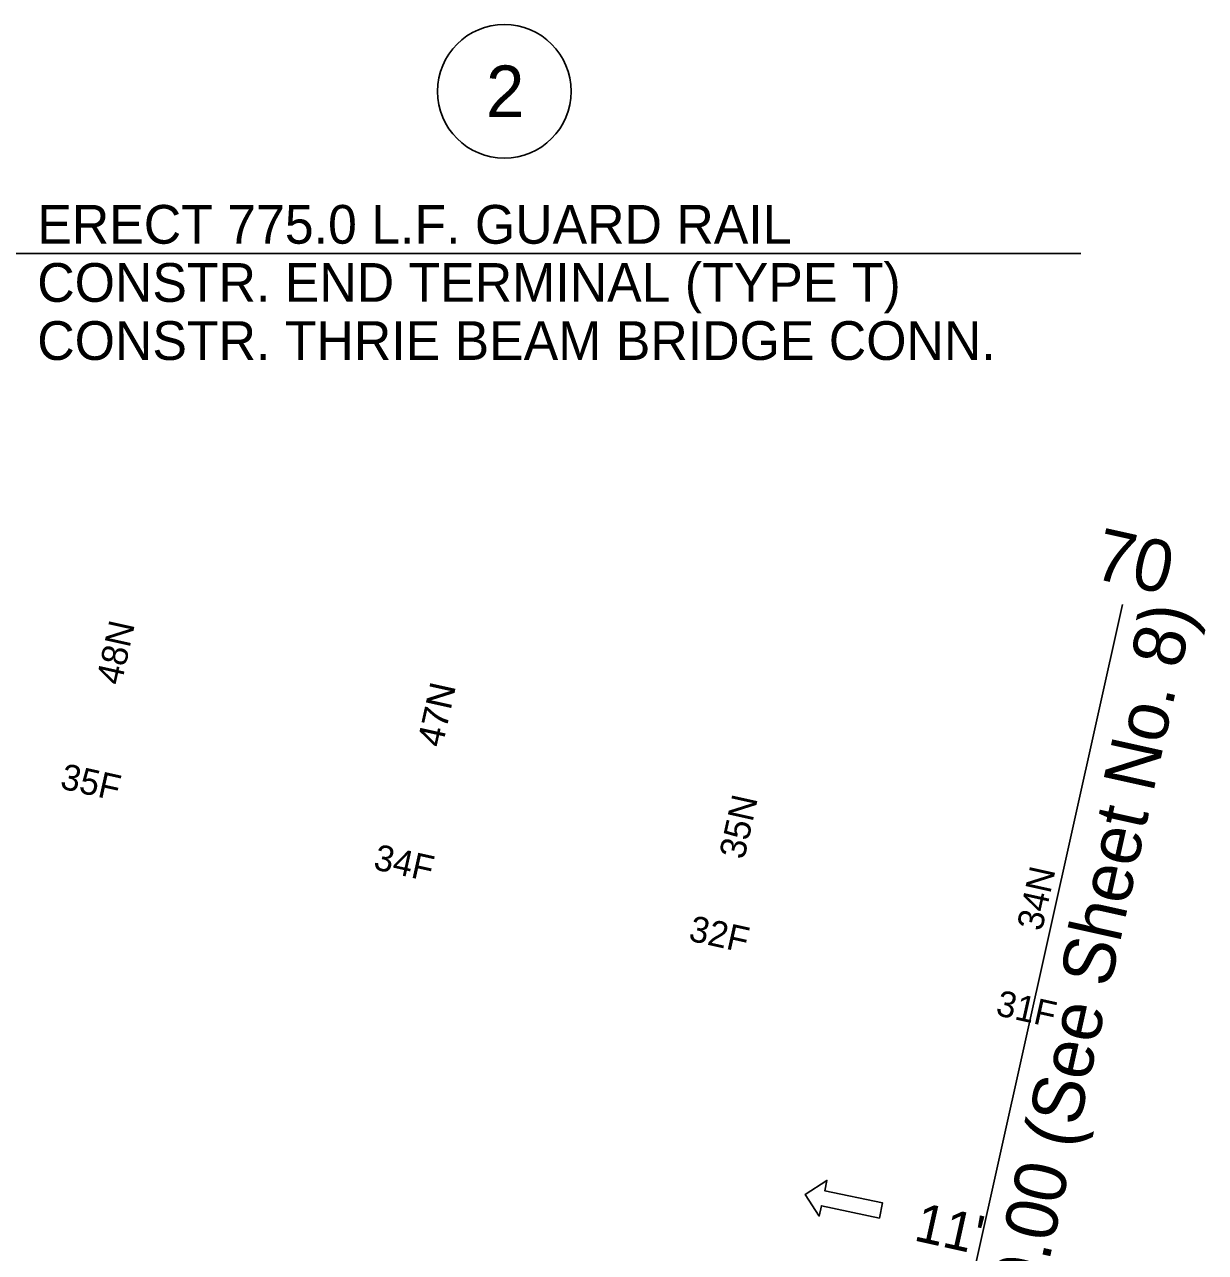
# Model space of a CAD drawing. Extents: x 1964849 to 1967422, y 1116563 to 1122210.
# Drawn here: x 1967169.6 to 1967352.5, y 1118419.5 to 1118609.7 of the extents above; entities that cross this region are included whole.
import ezdxf

# ---------------------------------------------------------------- set-up
doc = ezdxf.new("R2010")
doc.units = 0
for name, color, linetype in [('RD_EX_DV_TX_Prop', 7, 'Continuous'), ('RD_HC_TX_Sta50', 7, 'Continuous'), ('RD_PD_Final_LnLine', 7, 'Continuous'), ('RD_PD_Final_TX', 7, 'Continuous'), ('RD_PD_TX_CstnLmt', 7, 'Continuous'), ('RD_SHT_MatchLine', 7, 'Continuous'), ('RD_TX_Drainage', 7, 'Continuous'), ('RD_TX_Misc1', 7, 'Continuous')]:
    doc.layers.add(name, color=color, linetype=linetype)

msp = doc.modelspace()

# ---------------------------------------------------------------- linework, layer by layer
at = {"layer": 'RD_EX_DV_TX_Prop'}
msp.add_circle((1967243.94, 1118599.3), 10.35, dxfattribs=at)
at = {"layer": 'RD_PD_Final_LnLine'}
msp.add_lwpolyline([(1967302.03, 1118424.81), (1967302.52, 1118427.15), (1967293.55, 1118429.05), (1967293.89, 1118430.65), (1967290.54, 1118428.47), (1967292.72, 1118425.11), (1967293.05, 1118426.71)], close=True, dxfattribs=at)
at = {"layer": 'RD_SHT_MatchLine'}
msp.add_lwpolyline([(1967294.11, 1118314.83), (1967316.88, 1118417.33), (1967339.66, 1118519.83)], dxfattribs=at)
at = {"layer": 'RD_TX_Misc1'}
msp.add_line((1967333.2, 1118574.21), (1967166.6, 1118574.21), dxfattribs=at)

# ---------------------------------------------------------------- texts
at = {"layer": 'RD_EX_DV_TX_Prop'}
msp.add_text('2', height=8, dxfattribs=at).set_placement((1967241.1, 1118595.31))
at = {"layer": 'RD_HC_TX_Sta50'}
msp.add_text('70', height=8, rotation=347.4724, dxfattribs=at).set_placement((1967334.89, 1118523.96))
at = {"layer": 'RD_PD_Final_TX'}
msp.add_text("11'", height=6, rotation=347.4724, dxfattribs=at).set_placement((1967307.18, 1118421.39))
at = {"layer": 'RD_PD_TX_CstnLmt'}
for s, p in [('35F', (1967174.98, 1118491.37)), ('34F', (1967223.5, 1118478.87)), ('32F', (1967272.31, 1118467.82)), ('31F', (1967319.89, 1118456.27))]:
    msp.add_text(s, height=4, rotation=347.4724, dxfattribs=at).set_placement(p)
at = {"layer": 'RD_SHT_MatchLine'}
msp.add_text('Match Line Sta. 70+00.00 (See Sheet No. 8)', height=8, rotation=77.4724, dxfattribs=at).set_placement((1967305, 1118313.16))
at = {"layer": 'RD_TX_Drainage'}
for s, p in [('48N', (1967184.6, 1118507.2)), ('47N', (1967234.32, 1118497.57)), ('47N', (1967234.33, 1118497.62)), ('35N', (1967281.08, 1118480.23)), ('34N', (1967327.19, 1118469.13))]:
    msp.add_text(s, height=4, rotation=77.4724, dxfattribs=at).set_placement(p)
at = {"layer": 'RD_TX_Misc1'}
for s, p in [('ERECT 775.0 L.F. GUARD RAIL', (1967171.6, 1118575.71)), ('CONSTR. END TERMINAL (TYPE T)', (1967171.6, 1118566.71)), ('CONSTR. THRIE BEAM BRIDGE CONN.', (1967171.6, 1118557.71))]:
    msp.add_text(s, height=6, dxfattribs=at).set_placement(p)

doc.saveas('drawing.dxf')
